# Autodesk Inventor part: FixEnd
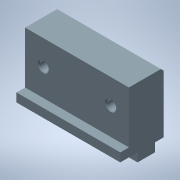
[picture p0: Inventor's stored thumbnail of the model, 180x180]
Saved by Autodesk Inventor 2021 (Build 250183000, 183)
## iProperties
Created: 2005-11
Part Number: FixEnd
Document SubType Name: Modeling
Designer: Administrator
Manufacturer: Standard
Standards Organization: Custom
Material: Generic
Density: 1 g/cm^3
Appearance: Light Steel Blue
Author: Administrator
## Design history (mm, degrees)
sketch "Sketch1"
  geometry: L1 (0, 0)-(60, 0); L2 (60, 0)-(60, -10); L3 (60, -10)-(0, -10); L4 (0, -10)-(0, 0)
  constraints: 8 end point, 2 parallel, 1 horizontal, 1 perpendicular
extrude "Extrusion1" new body sketch "Sketch1" stored distance "d2" = 5; taper "d3" = 0 deg
sketch "Sketch2"
  geometry: L1 (0, -20)-(60, -20); L2 (60, -20)-(60, 5); L3 (60, 5)-(0, 5); L4 (0, 5)-(0, -20)
  constraints: 8 end point, 2 parallel, 1 horizontal, 1 perpendicular
extrude "Extrusion2" join sketch "Sketch2" distance "d15" = 5; taper "d16" = 0 deg
sketch "Sketch3"
  geometry: L1 (0, -15)-(60, -15); L2 (60, -15)-(60, 5); L3 (60, 5)-(0, 5); L4 (0, 5)-(0, -15)
  constraints: 8 end point, 2 parallel, 1 horizontal, 1 perpendicular
extrude "Extrusion3" join sketch "Sketch3" distance "d21" = 30; taper "d22" = 0 deg
sketch "Sketch4"
  geometry: L1 (-60, 0)-(0, 0) reference; L2 (0, -10)-(-60, -10) reference; L3 (-30, 0)-(-30, -10); C1 r 2.5 at (-52.5, -5); C2 r 2.5 at (-7.5, -5)
  constraints: 2 centre point, 2 end point, 2 midpoint, 1 symmetric about line, 1 other
  dimensions: "d23" = 5 diameter of C1; "d24" = 7.5 horizontal distance of C1.centre L1.start; "d25" = 5 vertical distance of C1.centre L1.start
hole "Hole1" sketch "Sketch4" at (-7.5, -5), (-52.5, -5) diameter "d26" = 5; stored, may be unused: countersink angle "d30" = 90 deg, drill point angle "d32" = 118 deg; dims "d27" = 6, "d28" = 4, "d29" = 2, "d31" = 20
thread "Thread1" dims "d33" = 20, "d34" = 0
thread "Thread2" dims "d35" = 20, "d36" = 0
sketch "Sketch5"
  geometry: L1 (60, 0)-(0, 0) reference; L2 (0, -35)-(60, -35) reference; L3 (30, 0)-(30, -35); C1 r 2.7 at (10.5, -20.75); C2 r 2.7 at (49.5, -20.75)
  constraints: 2 centre point, 2 end point, 2 midpoint, 1 symmetric about line, 1 other
  dimensions: "d37" = 5.4 diameter of C1; "d38" = 10.5 horizontal distance of C1.centre L2.start; "d39" = 20.75 vertical distance of C1.centre L1.end
hole "Hole2" sketch "Sketch5" at (10.5, -20.75), (49.5, -20.75) diameter "d40" = 5.4; stored, may be unused: countersink angle "d44" = 90 deg, drill point angle "d46" = 118 deg; dims "d41" = 6, "d42" = 4, "d43" = 2, "d45" = 25
chamfer "Chamfer1" distance "d47" = 0.5; stored, may be unused: second distance "d48" = 2, angle "d49" = 45 deg
sketch "Sketch6"
  geometry: L1 (0, -35)-(60, -35) reference; L2 (0, 0)-(60, 0) reference; L3 (30, 0)-(30, -35); C1 r 2.7 at (10.5, -20.75) reference; C2 r 2.7 at (49.5, -20.75) reference; C3 r 4.25 at (10.5, -20.75); C4 r 4.25 at (49.5, -20.75)
  constraints: 2 centre point, 2 end point, 2 midpoint, 1 coincident, 1 symmetric about line, 1 other
  dimensions: "d50" = 8.5 diameter of C3; "d64" = 10.5 horizontal distance of C3.centre L2.start (derived); "d65" = 20.75 vertical distance of C3.centre L2.start (derived)
hole "Hole3" sketch "Sketch6" at (10.5, -20.75), (49.5, -20.75) diameter "d51" = 8.7; stored, may be unused: countersink angle "d55" = 90 deg, drill point angle "d57" = 0 deg; dims "d52" = 6, "d53" = 4, "d54" = 2, "d56" = 5.4
chamfer "Chamfer2" distance "d58" = 1.5; stored, may be unused: second distance "d59" = 2, angle "d60" = 45 deg
chamfer "Chamfer3" distance "d61" = 0.5; stored, may be unused: second distance "d62" = 2, angle "d63" = 45 deg
body "Solid1"
